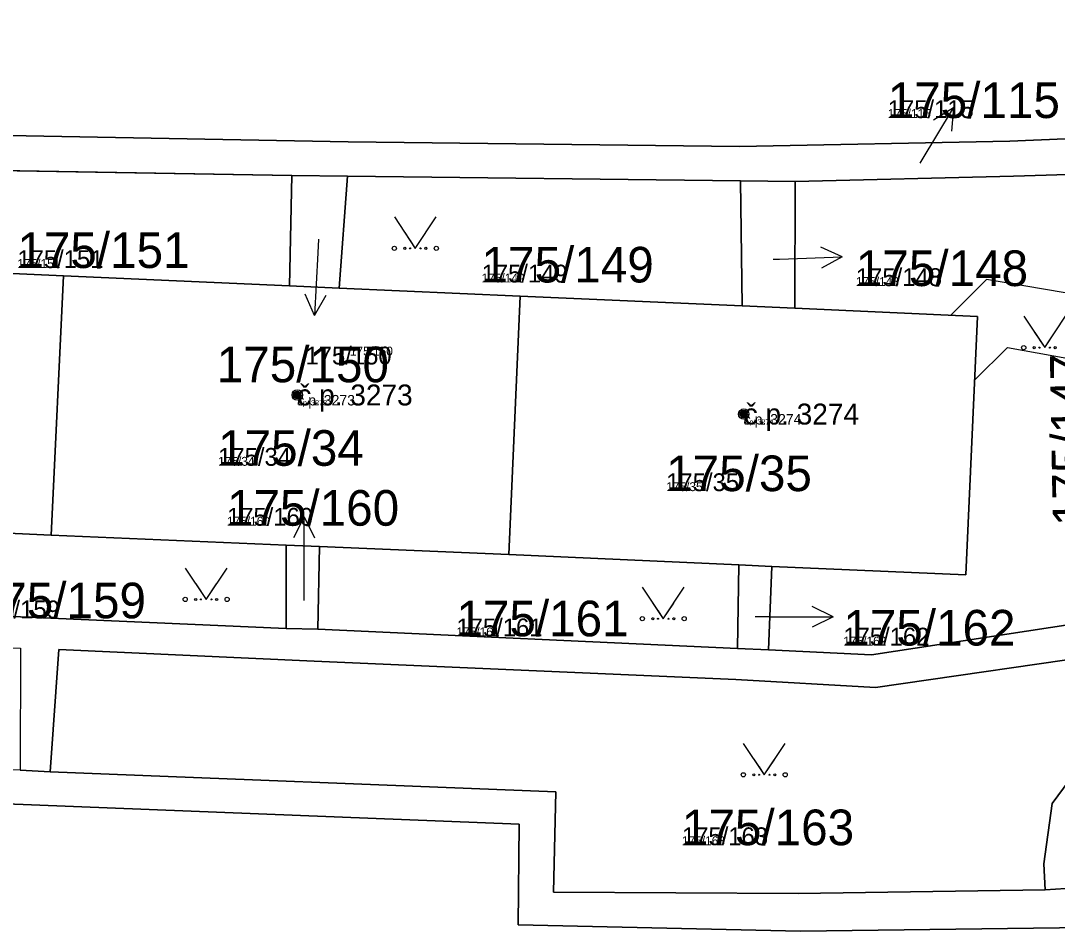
# Model space of a CAD drawing. Extents: x -759873 to -758487, y -975024 to -973516.
# Drawn here: x -759506.12 to -759456.66, y -974653.71 to -974610.24 of the extents above; entities that cross this region are included whole.
import ezdxf

# ---------------------------------------------------------------- set-up
doc = ezdxf.new("R2010")
doc.units = 0
for name, color, linetype in [('KAT_02_hranice parcel', 7, 'Continuous'), ('KAT_03_1000_st čísla parcelní', 7, 'Continuous'), ('KAT_03_1000_čísla parcelní', 7, 'Continuous'), ('KAT_03_1000_čísla popisná', 7, 'Continuous'), ('KAT_03_250_st čísla parcelní', 7, 'Continuous'), ('KAT_03_250_čísla parcelní', 7, 'Continuous'), ('KAT_03_250_čísla popisná', 7, 'Continuous'), ('KAT_03_500_st čísla parcelní', 7, 'Continuous'), ('KAT_03_500_čísla parcelní', 7, 'Continuous'), ('KAT_03_500_čísla popisná', 7, 'Continuous'), ('KAT_05_1000_značky kultur', 7, 'Continuous'), ('KAT_05_250_značky kultur', 7, 'Continuous'), ('KAT_05_500_značky kultur', 7, 'Continuous'), ('KAT_07_1000_značky budov', 7, 'Continuous'), ('KAT_07_250_značky budov', 7, 'Continuous'), ('KAT_07_500_značky budov', 7, 'Continuous'), ('KAT_10_věcná břemena', 7, 'Continuous'), ('KAT_12_pomocná šipka', 7, 'Continuous'), ('KAT_14_plocha_budovy', 7, 'Continuous'), ('KAT_14_plocha_pozemek', 7, 'Continuous')]:
    doc.layers.add(name, color=color, linetype=linetype)

msp = doc.modelspace()

# ---------------------------------------------------------------- linework, layer by layer
at = {"layer": 'KAT_02_hranice parcel'}
for p, q in [((-759512.66, -974617.3), (-759493.18, -974617.63)), ((-759493.18, -974617.63), (-759493.3, -974622.9)), ((-759493.18, -974617.63), (-759490.52, -974617.67)), ((-759490.52, -974617.67), (-759490.93, -974623.01)), ((-759490.52, -974617.67), (-759471.78, -974617.89)), ((-759471.78, -974617.89), (-759469.17, -974617.92)), ((-759471.78, -974617.89), (-759471.69, -974623.86)), ((-759469.17, -974617.92), (-759469.18, -974623.97)), ((-759504.08, -974622.42), (-759512.84, -974622.03)), ((-759504.66, -974634.8), (-759504.08, -974622.42)), ((-759493.3, -974622.9), (-759504.08, -974622.42)), ((-759490.93, -974623.01), (-759493.3, -974622.9)), ((-759482.28, -974623.39), (-759490.93, -974623.01)), ((-759482.83, -974635.73), (-759482.28, -974623.39)), ((-759471.69, -974623.86), (-759482.28, -974623.39)), ((-759469.18, -974623.97), (-759471.69, -974623.86)), ((-759513.93, -974634.37), (-759504.66, -974634.8)), ((-759504.66, -974634.8), (-759493.46, -974635.28)), ((-759493.46, -974635.28), (-759491.86, -974635.35)), ((-759493.45, -974639.25), (-759493.46, -974635.28)), ((-759491.95, -974639.29), (-759491.86, -974635.35)), ((-759491.86, -974635.35), (-759482.83, -974635.73)), ((-759482.83, -974635.73), (-759471.85, -974636.22)), ((-759471.91, -974640.21), (-759471.85, -974636.22)), ((-759471.85, -974636.22), (-759470.28, -974636.29)), ((-759470.28, -974636.29), (-759470.44, -974640.27)), ((-759493.45, -974639.25), (-759514.11, -974638.35)), ((-759491.95, -974639.29), (-759493.45, -974639.25)), ((-759471.91, -974640.21), (-759491.95, -974639.29)), ((-759470.44, -974640.27), (-759471.91, -974640.21)), ((-759506.15, -974646.02), (-759504.71, -974646.1)), ((-759457.23, -974651.73), (-759455.76, -974651.64))]:
    msp.add_line(p, q, dxfattribs=at)
for points in [[(-759748.01, -974589.58), (-759742.78, -974592.68), (-759732.01, -974598.91), (-759728.99, -974600.68), (-759725.4, -974602.45), (-759718.02, -974604.75), (-759709.84, -974606.71), (-759702.63, -974608.03), (-759689.82, -974608.95), (-759677.23, -974609.87), (-759664.06, -974610.49), (-759641.64, -974611.43), (-759620.48, -974612.36), (-759598.5, -974613.15), (-759577.03, -974613.93), (-759558.28, -974614.4), (-759534.22, -974615.1), (-759512.72, -974615.61), (-759490.5, -974616.02), (-759471.82, -974616.25), (-759458.92, -974616), (-759446.09, -974615.46)], [(-759453.56, -974617.5), (-759453.57, -974623.69), (-759453.57, -974630.65), (-759453.6, -974638.11), (-759453.76, -974638.72), (-759465.53, -974640.52), (-759470.44, -974640.27)], [(-759469.17, -974617.92), (-759458.75, -974617.66), (-759453.56, -974617.5)], [(-759470.28, -974636.29), (-759461.02, -974636.7), (-759460.47, -974624.36), (-759469.18, -974623.97)], [(-759504.71, -974646.1), (-759504.3, -974640.26), (-759492.11, -974640.81), (-759471.99, -974641.69), (-759465.33, -974642.08), (-759453.67, -974640.38), (-759453.66, -974641.58), (-759455.9, -974641.65), (-759455.97, -974643.55), (-759453.97, -974643.65), (-759456.9, -974647.61), (-759457.3, -974650.49), (-759457.23, -974651.73)], [(-759301.4, -974651.09), (-759309.93, -974650.8), (-759309.98, -974645.76), (-759323.06, -974645.78), (-759353.1, -974645.55), (-759386.38, -974645.33), (-759400.57, -974645.67), (-759414.93, -974646.26), (-759414.73, -974651.33), (-759436.14, -974652.5), (-759441.93, -974652.85), (-759450.38, -974653.47), (-759468.91, -974653.71), (-759482.38, -974653.4), (-759482.33, -974648.6), (-759512.45, -974647.4), (-759531.67, -974646.64), (-759556.45, -974645.57)], [(-759504.71, -974646.1), (-759480.58, -974647.06), (-759480.7, -974651.84), (-759469.03, -974651.9), (-759457.23, -974651.73)]]:
    msp.add_lwpolyline(points, dxfattribs=at)
at = {"layer": 'KAT_03_1000_čísla popisná'}
for centre in [(-759492.92, -974628.11), (-759471.62, -974629.02)]:
    msp.add_circle(centre, 0.25, dxfattribs=at)
at = {"layer": 'KAT_03_250_čísla popisná'}
for centre in [(-759492.92, -974628.11), (-759471.62, -974629.02)]:
    msp.add_circle(centre, 0.0625, dxfattribs=at)
at = {"layer": 'KAT_03_500_čísla popisná'}
for centre in [(-759492.92, -974628.11), (-759471.62, -974629.02)]:
    msp.add_circle(centre, 0.125, dxfattribs=at)
at = {"layer": 'KAT_05_1000_značky kultur'}
for points in [[(-759488.29, -974619.609), (-759487.29, -974621.11), (-759486.29, -974619.609)], [(-759458.26, -974624.349), (-759457.26, -974625.85), (-759456.26, -974624.349)], [(-759498.27, -974636.369), (-759497.27, -974637.87), (-759496.27, -974636.369)], [(-759476.46, -974637.289), (-759475.46, -974638.79), (-759474.46, -974637.289)], [(-759471.64, -974644.739), (-759470.64, -974646.24), (-759469.64, -974644.739)]]:
    msp.add_lwpolyline(points, dxfattribs=at)
for centre in [(-759488.29, -974621.109), (-759486.29, -974621.109), (-759458.26, -974625.849), (-759498.27, -974637.869), (-759496.27, -974637.869), (-759476.46, -974638.789), (-759474.46, -974638.789), (-759471.64, -974646.239), (-759469.64, -974646.239)]:
    msp.add_circle(centre, 0.1, dxfattribs=at)
at = {"layer": 'KAT_05_250_značky kultur'}
for points in [[(-759487.54, -974620.735), (-759487.29, -974621.11), (-759487.04, -974620.735)], [(-759457.51, -974625.475), (-759457.26, -974625.85), (-759457.01, -974625.475)], [(-759497.52, -974637.495), (-759497.27, -974637.87), (-759497.02, -974637.495)], [(-759475.71, -974638.415), (-759475.46, -974638.79), (-759475.21, -974638.415)], [(-759470.89, -974645.865), (-759470.64, -974646.24), (-759470.39, -974645.865)]]:
    msp.add_lwpolyline(points, dxfattribs=at)
for centre in [(-759487.54, -974621.11), (-759487.04, -974621.11), (-759457.51, -974625.85), (-759457.01, -974625.85), (-759497.52, -974637.87), (-759497.02, -974637.87), (-759475.71, -974638.79), (-759475.21, -974638.79), (-759470.89, -974646.24), (-759470.39, -974646.24)]:
    msp.add_circle(centre, 0.025, dxfattribs=at)
at = {"layer": 'KAT_05_500_značky kultur'}
for points in [[(-759487.79, -974620.36), (-759487.29, -974621.11), (-759486.79, -974620.36)], [(-759457.76, -974625.1), (-759457.26, -974625.85), (-759456.76, -974625.1)], [(-759497.77, -974637.12), (-759497.27, -974637.87), (-759496.77, -974637.12)], [(-759475.96, -974638.04), (-759475.46, -974638.79), (-759474.96, -974638.04)], [(-759471.14, -974645.49), (-759470.64, -974646.24), (-759470.14, -974645.49)]]:
    msp.add_lwpolyline(points, dxfattribs=at)
for centre in [(-759487.79, -974621.11), (-759486.79, -974621.11), (-759457.76, -974625.85), (-759456.76, -974625.85), (-759497.77, -974637.87), (-759496.77, -974637.87), (-759475.96, -974638.79), (-759474.96, -974638.79), (-759471.14, -974646.24), (-759470.14, -974646.24)]:
    msp.add_circle(centre, 0.05, dxfattribs=at)
at = {"layer": 'KAT_07_1000_značky budov'}
for centre in [(-759492.927, -974628.109), (-759471.627, -974629.019)]:
    msp.add_circle(centre, 0.175, dxfattribs=at)
at = {"layer": 'KAT_07_250_značky budov'}
for centre in [(-759492.922, -974628.11), (-759471.622, -974629.02)]:
    msp.add_circle(centre, 0.0437, dxfattribs=at)
at = {"layer": 'KAT_07_500_značky budov'}
for centre in [(-759492.923, -974628.11), (-759471.623, -974629.02)]:
    msp.add_circle(centre, 0.0875, dxfattribs=at)
at = {"layer": 'KAT_10_věcná břemena'}
msp.add_lwpolyline([(-759461.74, -974624.3), (-759460.47, -974624.36), (-759460.61, -974627.41), (-759459.04, -974625.84), (-759453.82, -974626.79), (-759453.57, -974626.79), (-759452.1, -974626.79), (-759452.1, -974623.73), (-759453.57, -974623.69), (-759460.04, -974622.6)], close=True, dxfattribs=at)
at = {"layer": 'KAT_12_pomocná šipka'}
for p, q in [((-759463.16, -974616.97), (-759461.614, -974614.398)), ((-759461.614, -974614.398), (-759462.559, -974614.998)), ((-759461.614, -974614.398), (-759461.701, -974615.514)), ((-759463.2, -974617.04), (-759463.16, -974616.97)), ((-759491.91, -974620.68), (-759491.94, -974621.32)), ((-759466.921, -974621.515), (-759467.939, -974621.05)), ((-759491.94, -974621.32), (-759492.097, -974624.317)), ((-759470.21, -974621.63), (-759469.92, -974621.62)), ((-759469.92, -974621.62), (-759466.921, -974621.515)), ((-759466.921, -974621.515), (-759467.904, -974622.051)), ((-759492.097, -974624.317), (-759492.545, -974623.291)), ((-759492.097, -974624.317), (-759491.545, -974623.343)), ((-759492.6, -974633.929), (-759493.101, -974634.93)), ((-759492.6, -974636.93), (-759492.6, -974633.929)), ((-759492.6, -974633.929), (-759492.099, -974634.93)), ((-759492.6, -974637.92), (-759492.6, -974636.93)), ((-759467.349, -974638.7), (-759468.35, -974638.199)), ((-759470.35, -974638.7), (-759471.08, -974638.7)), ((-759470.35, -974638.7), (-759467.349, -974638.7)), ((-759467.349, -974638.7), (-759468.35, -974639.201))]:
    msp.add_line(p, q, dxfattribs=at)
at = {"layer": 'KAT_14_plocha_budovy'}
for points in [[(-759504.66, -974634.8), (-759504.08, -974622.42), (-759512.84, -974622.03), (-759515.31, -974621.93), (-759525.88, -974621.46), (-759526.43, -974633.8), (-759515.51, -974634.3), (-759513.93, -974634.37)], [(-759493.46, -974635.28), (-759491.86, -974635.35), (-759482.83, -974635.73), (-759482.28, -974623.39), (-759490.93, -974623.01), (-759493.3, -974622.9), (-759504.08, -974622.42), (-759504.66, -974634.8)], [(-759482.83, -974635.73), (-759471.85, -974636.22), (-759470.28, -974636.29), (-759461.02, -974636.7), (-759460.47, -974624.36), (-759469.18, -974623.97), (-759471.69, -974623.86), (-759482.28, -974623.39)]]:
    msp.add_lwpolyline(points, close=True, dxfattribs=at)
at = {"layer": 'KAT_14_plocha_pozemek'}
for points in [[(-759446.09, -974615.46), (-759458.92, -974616), (-759471.82, -974616.25), (-759490.5, -974616.02), (-759512.72, -974615.61), (-759534.22, -974615.1), (-759558.28, -974614.4), (-759577.03, -974613.93), (-759598.5, -974613.15), (-759620.48, -974612.36)], [(-759620.48, -974612.36), (-759598.5, -974613.15), (-759577.03, -974613.93), (-759558.28, -974614.4), (-759534.22, -974615.1), (-759512.72, -974615.61), (-759490.5, -974616.02), (-759471.82, -974616.25), (-759458.92, -974616), (-759446.09, -974615.46)], [(-759453.76, -974638.72), (-759465.53, -974640.52), (-759470.44, -974640.27), (-759471.91, -974640.21), (-759491.95, -974639.29), (-759493.45, -974639.25), (-759514.11, -974638.35), (-759515.58, -974638.24), (-759535.52, -974637.39), (-759537, -974637.31), (-759554.69, -974636.59), (-759554, -974616.28), (-759554.99, -974616.21), (-759555.69, -974636.55), (-759578.04, -974635.54), (-759579.84, -974635.44), (-759599.58, -974634.68), (-759601.39, -974634.57), (-759621.66, -974633.76)], [(-759554.99, -974616.21), (-759554, -974616.28), (-759536.47, -974616.69), (-759534.22, -974616.74), (-759515.27, -974617.19), (-759512.66, -974617.3), (-759493.18, -974617.63), (-759490.52, -974617.67), (-759471.78, -974617.89), (-759469.17, -974617.92), (-759458.75, -974617.66), (-759453.56, -974617.5)], [(-759608.73, -974635.83), (-759601.54, -974636.08), (-759585.21, -974636.67), (-759576.31, -974637.16), (-759576.61, -974642.92), (-759575.19, -974642.84), (-759574.86, -974637.22), (-759556.11, -974638.04), (-759556.4, -974643.92), (-759554.75, -974643.98), (-759554.51, -974638.11), (-759537.36, -974638.86), (-759515.58, -974639.78), (-759506.13, -974640.2), (-759506.15, -974646.02), (-759504.71, -974646.1), (-759504.3, -974640.26), (-759492.11, -974640.81), (-759471.99, -974641.69), (-759465.33, -974642.08), (-759453.67, -974640.38)], [(-759450.38, -974653.47), (-759468.91, -974653.71), (-759482.38, -974653.4), (-759482.33, -974648.6), (-759512.45, -974647.4), (-759531.67, -974646.64), (-759556.45, -974645.57), (-759559.25, -974645.05), (-759559.6, -974650.39), (-759571.57, -974649.69), (-759577.12, -974649.37), (-759576.85, -974644.52), (-759594.91, -974643.96), (-759630.55, -974642.48)], [(-759455.76, -974651.64), (-759457.23, -974651.73), (-759469.03, -974651.9), (-759480.7, -974651.84), (-759480.58, -974647.06), (-759504.71, -974646.1), (-759506.15, -974646.02), (-759531.77, -974645.02), (-759554.75, -974643.98), (-759556.4, -974643.92), (-759556.45, -974645.57), (-759531.67, -974646.64), (-759512.45, -974647.4), (-759482.33, -974648.6), (-759482.38, -974653.4), (-759468.91, -974653.71), (-759450.38, -974653.47)], [(-759453.97, -974643.65), (-759456.9, -974647.61), (-759457.3, -974650.49), (-759457.23, -974651.73), (-759455.76, -974651.64)]]:
    msp.add_lwpolyline(points, dxfattribs=at)
for points in [[(-759512.66, -974617.3), (-759512.84, -974622.03), (-759504.08, -974622.42), (-759493.3, -974622.9), (-759493.18, -974617.63)], [(-759493.18, -974617.63), (-759493.3, -974622.9), (-759490.93, -974623.01), (-759490.52, -974617.67)], [(-759490.52, -974617.67), (-759490.93, -974623.01), (-759482.28, -974623.39), (-759471.69, -974623.86), (-759471.78, -974617.89)], [(-759469.17, -974617.92), (-759469.18, -974623.97), (-759460.47, -974624.36), (-759461.02, -974636.7), (-759470.28, -974636.29), (-759470.44, -974640.27), (-759465.53, -974640.52), (-759453.76, -974638.72), (-759453.6, -974638.11), (-759453.57, -974630.65), (-759453.57, -974623.69), (-759453.56, -974617.5), (-759458.75, -974617.66)], [(-759471.69, -974623.86), (-759469.18, -974623.97), (-759469.17, -974617.92), (-759471.78, -974617.89)], [(-759512.84, -974622.03), (-759515.31, -974621.93), (-759525.88, -974621.46), (-759526.43, -974633.8), (-759515.51, -974634.3), (-759513.93, -974634.37), (-759504.66, -974634.8), (-759504.08, -974622.42)], [(-759482.28, -974623.39), (-759490.93, -974623.01), (-759493.3, -974622.9), (-759504.08, -974622.42), (-759504.66, -974634.8), (-759493.46, -974635.28), (-759491.86, -974635.35), (-759482.83, -974635.73)], [(-759460.47, -974624.36), (-759469.18, -974623.97), (-759471.69, -974623.86), (-759482.28, -974623.39), (-759482.83, -974635.73), (-759471.85, -974636.22), (-759470.28, -974636.29), (-759461.02, -974636.7)], [(-759493.45, -974639.25), (-759493.46, -974635.28), (-759504.66, -974634.8), (-759513.93, -974634.37), (-759514.11, -974638.35)], [(-759491.86, -974635.35), (-759493.46, -974635.28), (-759493.45, -974639.25), (-759491.95, -974639.29)], [(-759471.85, -974636.22), (-759482.83, -974635.73), (-759491.86, -974635.35), (-759491.95, -974639.29), (-759471.91, -974640.21)], [(-759470.28, -974636.29), (-759471.85, -974636.22), (-759471.91, -974640.21), (-759470.44, -974640.27)], [(-759469.03, -974651.9), (-759457.23, -974651.73), (-759457.3, -974650.49), (-759456.9, -974647.61), (-759453.97, -974643.65), (-759455.97, -974643.55), (-759455.9, -974641.65), (-759453.66, -974641.58), (-759453.67, -974640.38), (-759465.33, -974642.08), (-759471.99, -974641.69), (-759492.11, -974640.81), (-759504.3, -974640.26), (-759504.71, -974646.1), (-759480.58, -974647.06), (-759480.7, -974651.84)]]:
    msp.add_lwpolyline(points, close=True, dxfattribs=at)

# ---------------------------------------------------------------- texts
at = {"layer": 'KAT_03_1000_st čísla parcelní'}
for s, p in [('175/34', (-759496.7, -974631.49)), ('175/35', (-759475.32, -974632.7))]:
    msp.add_text(s, height=1.7, dxfattribs=at).set_placement(p)
at = {"layer": 'KAT_03_1000_čísla parcelní'}
for s, p in [('175/115', (-759464.75, -974614.89)), ('175/151', (-759506.28, -974622.049)), ('175/149', (-759484.13, -974622.74)), ('175/148', (-759466.27, -974622.91)), ('175/150', (-759496.766, -974627.503)), ('175/160', (-759496.28, -974634.35)), ('175/159', (-759508.36, -974638.77)), ('175/161', (-759485.33, -974639.63)), ('175/162', (-759466.87, -974640.07)), ('175/163', (-759474.57, -974649.6))]:
    msp.add_text(s, height=1.7, dxfattribs=at).set_placement(p)
msp.add_text('175/147', height=1.7, rotation=91, dxfattribs=at).set_placement((-759455.17, -974634.345))
at = {"layer": 'KAT_03_1000_čísla popisná'}
for s, p in [('č.p. 3273', (-759492.92, -974628.61)), ('č.p. 3274', (-759471.62, -974629.52))]:
    msp.add_text(s, height=1, dxfattribs=at).set_placement(p)
at = {"layer": 'KAT_03_250_st čísla parcelní'}
for s, p in [('175/34', (-759496.7, -974631.49)), ('175/35', (-759475.32, -974632.7))]:
    msp.add_text(s, height=0.425, dxfattribs=at).set_placement(p)
at = {"layer": 'KAT_03_250_čísla parcelní'}
for s, p in [('175/115', (-759464.75, -974614.89)), ('175/151', (-759506.28, -974622.049)), ('175/149', (-759484.13, -974622.74)), ('175/148', (-759466.27, -974622.91)), ('175/150', (-759490.415, -974626.228)), ('175/160', (-759496.28, -974634.35)), ('175/161', (-759485.33, -974639.63)), ('175/162', (-759466.87, -974640.07)), ('175/163', (-759474.57, -974649.6))]:
    msp.add_text(s, height=0.425, dxfattribs=at).set_placement(p)
at = {"layer": 'KAT_03_250_čísla popisná'}
for s, p in [('č.p. 3273', (-759492.92, -974628.61)), ('č.p. 3274', (-759471.62, -974629.52))]:
    msp.add_text(s, height=0.25, dxfattribs=at).set_placement(p)
at = {"layer": 'KAT_03_500_st čísla parcelní'}
for s, p in [('175/34', (-759496.7, -974631.49)), ('175/35', (-759475.32, -974632.7))]:
    msp.add_text(s, height=0.85, dxfattribs=at).set_placement(p)
at = {"layer": 'KAT_03_500_čísla parcelní'}
for s, p in [('175/115', (-759464.75, -974614.89)), ('175/151', (-759506.28, -974622.049)), ('175/149', (-759484.13, -974622.74)), ('175/148', (-759466.27, -974622.91)), ('175/150', (-759492.532, -974626.653)), ('175/160', (-759496.28, -974634.35)), ('175/159', (-759508.36, -974638.77)), ('175/161', (-759485.33, -974639.63)), ('175/162', (-759466.87, -974640.07)), ('175/163', (-759474.57, -974649.6))]:
    msp.add_text(s, height=0.85, dxfattribs=at).set_placement(p)
at = {"layer": 'KAT_03_500_čísla popisná'}
for s, p in [('č.p. 3273', (-759492.92, -974628.61)), ('č.p. 3274', (-759471.62, -974629.52))]:
    msp.add_text(s, height=0.5, dxfattribs=at).set_placement(p)

doc.saveas('drawing.dxf')
